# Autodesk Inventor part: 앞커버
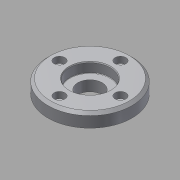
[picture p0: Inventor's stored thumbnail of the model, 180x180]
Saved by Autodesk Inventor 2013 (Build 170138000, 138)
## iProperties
Created: 2015-09
Part Number: 앞커버
Material: 알루미늄 6061
Document SubType Name: Modeling
Designer: mduedu
Density: 1 g/cm^3
Author: mduedu
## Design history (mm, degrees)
sketch "스케치1"
  geometry: L1 (0, 7.5)-(0, -7.5); L2 (0, 7.5)-(31, 7.5); L3 (31, 7.5)-(31, -2.5); L4 (31, -2.5)-(17.5, -2.5); L5 (17.5, -2.5)-(17.5, -7.5); L6 (17.5, -7.5)-(0, -7.5); 2 further points
  constraints: 12 end point, 2 parallel, 2 perpendicular, 1 coincident, 1 horizontal, 1 midpoint, 1 vertical
  dimensions: "d0" = 15 distance of L1.start L1.end; "d1" = 62 diameter of L3 L1; "d2" = 35 diameter of L5 L1; "d3" = 10 distance of L2.end L3.end
revolve "회전1" sketch "스케치1" stored, may be unused: angle "d4" = 90 deg
hole "구멍1" diameter "d7" = 30; stored, may be unused: countersink angle "d11" = 90 deg, drill point angle "d13" = 0 deg; dims "d5" = 10, "d6" = 10, "d8" = 6, "d9" = 4, "d10" = 2, "d12" = 7.3
hole "구멍2" diameter "d16" = 18; stored, may be unused: countersink angle "d20" = 90 deg, drill point angle "d22" = 0 deg; dims "d14" = 10, "d15" = 10, "d17" = 6, "d18" = 4, "d19" = 2, "d21" = 7.3
chamfer "모따기1" distance "d23" = 2; stored, may be unused: second distance "d24" = 2, angle "d25" = 45 deg
chamfer "모따기2" distance "d26" = 0.7; stored, may be unused: second distance "d27" = 2, angle "d28" = 30 deg
fillet "모깎기1" dims "d29" = 0.3
sketch "스케치2" dims "d30" = 45
  geometry: 6 further points
  constraints: 2 vertical alignment, 1 coincident, 7 other
  dimensions: "d34" = 360 deg dimension on point (0, 0) point (0, 22.5) (derived)
sketch "스케치3"
  geometry: 4 further points
hole "구멍3" sketch "스케치3" at (0, 22.5), (-22.5, 0), (22.5, 0), (0, -22.5) diameter "d36" = 4.5; stored, may be unused: countersink angle "d40" = 90 deg, drill point angle "d42" = 0 deg; dims "d37" = 6, "d38" = 8, "d39" = 4.6, "d41" = 8
node "솔리드1"
